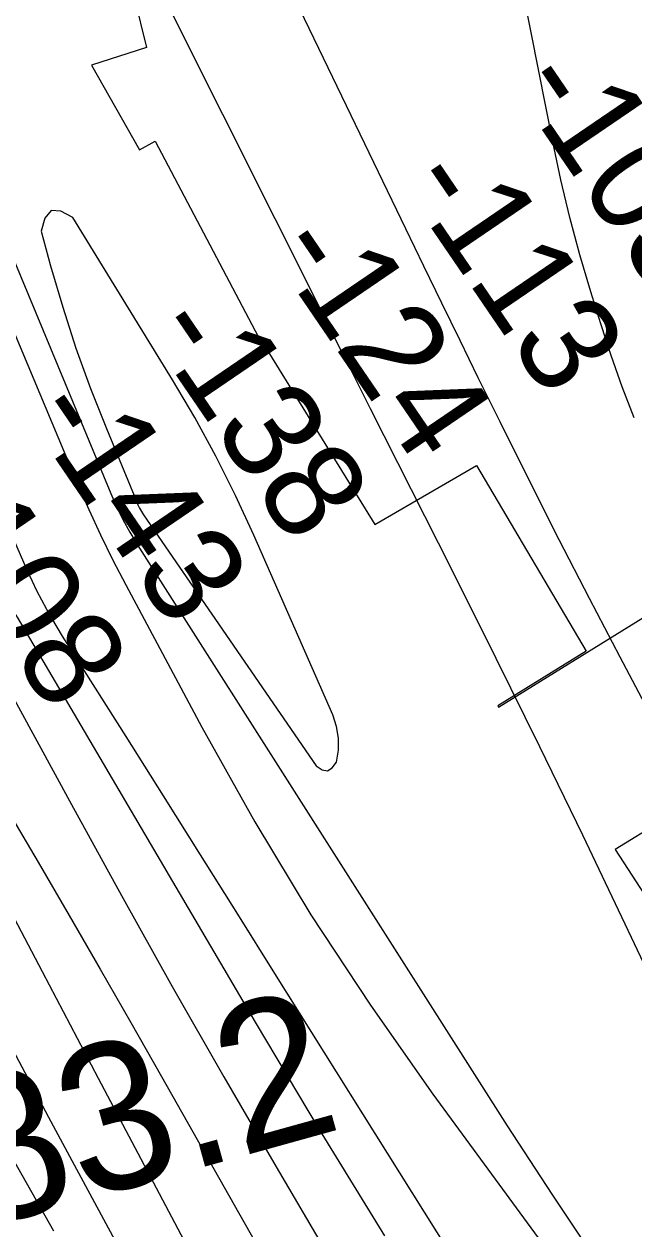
# Model space of a CAD drawing. Extents: x 3297772 to 3335630, y 634068 to 659439.
# Drawn here: x 3313036 to 3313452, y 651834 to 652655 of the extents above; entities that cross this region are included whole.
import ezdxf

# ---------------------------------------------------------------- set-up
doc = ezdxf.new("R2010")
doc.units = 0
for name, color, linetype in [('V-RIVR-RANG', 7, 'Continuous'), ('V-RRAP-RVMT', 7, 'Continuous'), ('V-SURV-IDEN', 7, 'Continuous'), ('V-TOPO-MAJR', 7, 'Continuous'), ('V-TOPO-MINR', 7, 'Continuous')]:
    doc.layers.add(name, color=color, linetype=linetype)

msp = doc.modelspace()

# ---------------------------------------------------------------- linework, layer by layer
at = {"layer": 'V-RRAP-RVMT'}
for p, q in [((3313087.7, 652767.9), (3313119.82, 652638.65)), ((3313119.82, 652638.65), (3313082.32, 652626.62)), ((3313082.32, 652626.62), (3313115.11, 652568.89)), ((3313115.11, 652568.89), (3313125.63, 652574.69)), ((3313125.63, 652574.69), (3313198.07, 652437.31)), ((3313198.07, 652437.31), (3313198.73, 652437.71)), ((3313198.73, 652437.71), (3313275.2, 652313.66)), ((3313275.2, 652313.66), (3313344.54, 652353.88)), ((3313344.54, 652353.88), (3313419.22, 652227.29)), ((3313359.44, 652189.2), (3313457.85, 652249.92)), ((3313419.22, 652227.29), (3313358.96, 652190.07)), ((3313358.96, 652190.07), (3313359.44, 652189.2)), ((3313524.91, 652145.06), (3313438.82, 652092.25)), ((3313438.82, 652092.25), (3313507.61, 651985.81))]:
    msp.add_line(p, q, dxfattribs=at)
at = {"layer": 'V-TOPO-MAJR'}
for points in [[(3313056.6, 651831.99), (3312877.88, 652148.31), (3312876.47, 652150.83), (3312874.71, 652154.02), (3312872.73, 652157.82), (3312871.37, 652160.72), (3312870.94, 652161.7), (3312868.51, 652167.39), (3312866.89, 652171.23), (3312865.29, 652175.08), (3312863.73, 652178.94), (3312862.19, 652182.81), (3312479.78, 653155.2)], [(3312735.31, 652911.59), (3312885.38, 652558.05), (3312907.05, 652508.22), (3312929.29, 652458.65), (3312952.38, 652409.48), (3312976.05, 652360.56), (3313017.69, 652276.37), (3313021.03, 652269.79), (3313024.47, 652263.25), (3313028.05, 652256.8), (3313031.71, 652250.39), (3313193.7, 651974.54), (3313237.42, 651901.45), (3313281.91, 651828.84)]]:
    msp.add_lwpolyline(points, dxfattribs=at)
at = {"layer": 'V-TOPO-MINR'}
for points in [[(3312778.69, 653362.54), (3312777.67, 653359.92), (3312777.13, 653357.03), (3312774.92, 653279.51), (3312775.07, 653271.29), (3312775.72, 653263.13), (3312777.14, 653255.07), (3312779.05, 653247.07), (3312858.18, 652973.64), (3312892.58, 652861.87), (3312929.45, 652750.98), (3312970.05, 652641.38), (3313013.11, 652532.66), (3313095.44, 652334.66), (3313099.44, 652325.71), (3313103.73, 652316.92), (3313108.47, 652308.37), (3313113.51, 652299.97), (3313365.34, 651903.93), (3313395.72, 651857.28), (3313426.75, 651811.08), (3313458.77, 651765.55)], [(3313471.96, 652166.95), (3313442.26, 652223.29), (3313421.45, 652263.16), (3313400.86, 652303.15), (3313380.59, 652343.3), (3313360.55, 652383.56), (3313345.74, 652413.61), (3313333.29, 652438.95), (3313320.9, 652464.31), (3313308.57, 652489.71), (3313296.3, 652515.12), (3313243.56, 652624.72), (3313204.93, 652704.94), (3313166.25, 652785.14), (3313127.51, 652865.32), (3313088.74, 652945.47), (3312933.52, 653266), (3312925.54, 653282.51), (3312917.58, 653299.02), (3312909.65, 653315.55), (3312901.73, 653332.08), (3312892.2, 653352.02), (3312889.08, 653358.6), (3312885.97, 653365.18)], [(3312680.03, 653217.52), (3312990.63, 652398.14), (3312998.65, 652377.41), (3313006.86, 652356.76), (3313015.34, 652336.22), (3313024.02, 652315.75), (3313035.98, 652288.04), (3313038.88, 652281.52), (3313041.87, 652275.04), (3313045.01, 652268.63), (3313048.24, 652262.27), (3313051.61, 652255.98), (3313055.09, 652249.75), (3313058.72, 652243.6), (3313062.46, 652237.52), (3313105.66, 652169.04), (3313131.04, 652128.75), (3313156.41, 652088.45), (3313181.73, 652048.11), (3313207.03, 652007.76), (3313410.76, 651682.46)], [(3312724.63, 653173.42), (3313072.87, 652341.34), (3313080.48, 652323.84), (3313088.43, 652306.5), (3313096.86, 652289.39), (3313105.62, 652272.43), (3313157.43, 652175.5), (3313193.67, 652111.03), (3313231.69, 652047.68), (3313272.36, 651986), (3313314.8, 651925.43), (3313520.68, 651644.55)], [(3313098.53, 651825.77), (3313069.2, 651879.93), (3313053.27, 651909.51), (3313028.9, 651955.33), (3313004.85, 652001.32), (3312981.28, 652047.56), (3312958.03, 652093.96), (3312934.34, 652141.88), (3312923.36, 652164.53), (3312912.6, 652187.29), (3312902.2, 652210.21), (3312892.03, 652233.24), (3312678.38, 652727.1)], [(3312755.07, 652713.94), (3312952.78, 652260.66), (3312960.68, 652242.99), (3312968.79, 652225.42), (3312977.22, 652207.99), (3312985.85, 652190.67), (3312994.8, 652173.51), (3313003.93, 652156.45), (3313013.37, 652139.55), (3313022.99, 652122.76), (3313045.95, 652083.51), (3313067.13, 652047.13), (3313088.2, 652010.69), (3313109.12, 651974.17), (3313129.94, 651937.58), (3313222.19, 651774.69)], [(3312729.4, 652695.22), (3312763.57, 652617.31), (3312939.16, 652219.47), (3312941.6, 652214.09), (3312944.11, 652208.75), (3312946.73, 652203.46), (3312949.42, 652198.21), (3313039.26, 652027.17), (3313086.98, 651936.45), (3313134.77, 651845.77), (3313182.66, 651755.14)], [(3313451.81, 652386.32), (3313443.65, 652407.46), (3313436.14, 652428.83), (3313429.05, 652450.37), (3313422.29, 652472.02), (3313414.84, 652497.33), (3313407.94, 652522.79), (3313401.88, 652548.45), (3313396.36, 652574.25), (3313376.93, 652673.04)], [(3312808.55, 652668.87), (3312855.41, 652562.96), (3312903.38, 652457.51), (3312982.89, 652286.25), (3312992.11, 652266.89), (3313001.56, 652247.65), (3313011.38, 652228.59), (3313021.44, 652209.65), (3313068.65, 652122.81), (3313102.8, 652060.71), (3313137.36, 651998.84), (3313172.52, 651937.32), (3313208.08, 651876.02), (3313424.67, 651506.94)], [(3313479.53, 651970.01), (3313445.83, 652041.26), (3313416.9, 652101.81), (3313387.67, 652162.2), (3313357.97, 652222.36), (3313327.95, 652282.37), (3313272.43, 652392.3), (3313265.07, 652406.89), (3313257.72, 652421.48), (3313250.39, 652436.08), (3313243.07, 652450.69), (3313136.24, 652664.12)], [(3313054.8, 652527.47), (3313050.63, 652522.33), (3313048.08, 652513.45), (3313054.53, 652489.89), (3313062.81, 652461.74), (3313071.78, 652433.82), (3313081.78, 652406.25), (3313092.47, 652378.92), (3313112.89, 652329.45), (3313113.96, 652327.07), (3313115.13, 652324.74), (3313116.44, 652322.49), (3313117.85, 652320.29), (3313235.27, 652149.08), (3313239.33, 652146.54), (3313243.06, 652145.81), (3313246.32, 652147.78), (3313249.25, 652151.55), (3313250.49, 652159.81), (3313250.64, 652167.97), (3313249.17, 652176), (3313246.61, 652183.94), (3313192.92, 652306.3), (3313180.33, 652333.46), (3313167.01, 652360.24), (3313152.6, 652386.45), (3313137.47, 652412.28), (3313069.62, 652522.79), (3313061.4, 652527), (3313054.8, 652527.47)]]:
    msp.add_lwpolyline(points, dxfattribs=at)

# ---------------------------------------------------------------- texts
at = {"layer": 'V-RIVR-RANG'}
for s, p in [('-105', (3313368.35, 652612.75)), ('-113', (3313293.02, 652545.72)), ('-124', (3313202.68, 652500.71)), ('-138', (3313119.17, 652445.67)), ('-143', (3313037.01, 652388.66)), ('-108', (3312955.14, 652331.22))]:
    msp.add_text(s, height=67, rotation=304.28817, dxfattribs=at).set_placement(p)
at = {"layer": 'V-SURV-IDEN'}
msp.add_text('4494+83.2', height=100, rotation=15.53694, dxfattribs=at).set_placement((3312642.77, 651732.41))

doc.saveas('drawing.dxf')
